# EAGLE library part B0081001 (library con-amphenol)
AMPHENOL CONNECTOR
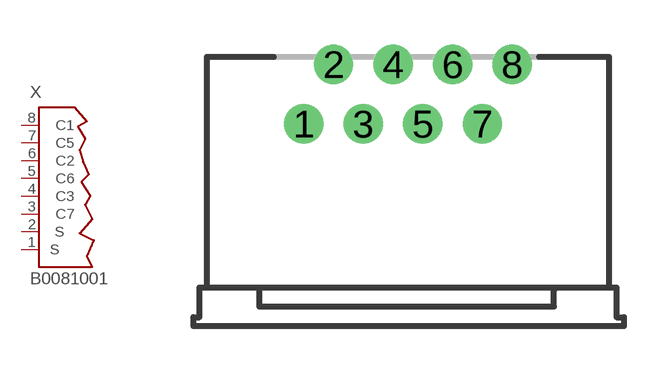
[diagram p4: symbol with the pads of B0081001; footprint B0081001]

Designator prefix X

## B0081001 (MF: AMPHENOL; MPN: C00710B0081001; OC_FARNELL: unknown; OC_NEWARK: 69H0124)  [B0081001]
1  S1  pas
2  S2  pas
3  C7  pas
4  C3  pas
5  C6  pas
6  C2  pas
7  C5  pas
8  C1  pas

## Footprint B0081001 (pad centres in mm)
AMPHENOL CONNECTOR
drill 0.813 round: 1 -3.5,-1; 2 -2.5,1; 3 -1.5,-1; 4 -0.5,1; 5 0.5,-1; 6 1.5,1; 7 2.5,-1; 8 3.5,1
